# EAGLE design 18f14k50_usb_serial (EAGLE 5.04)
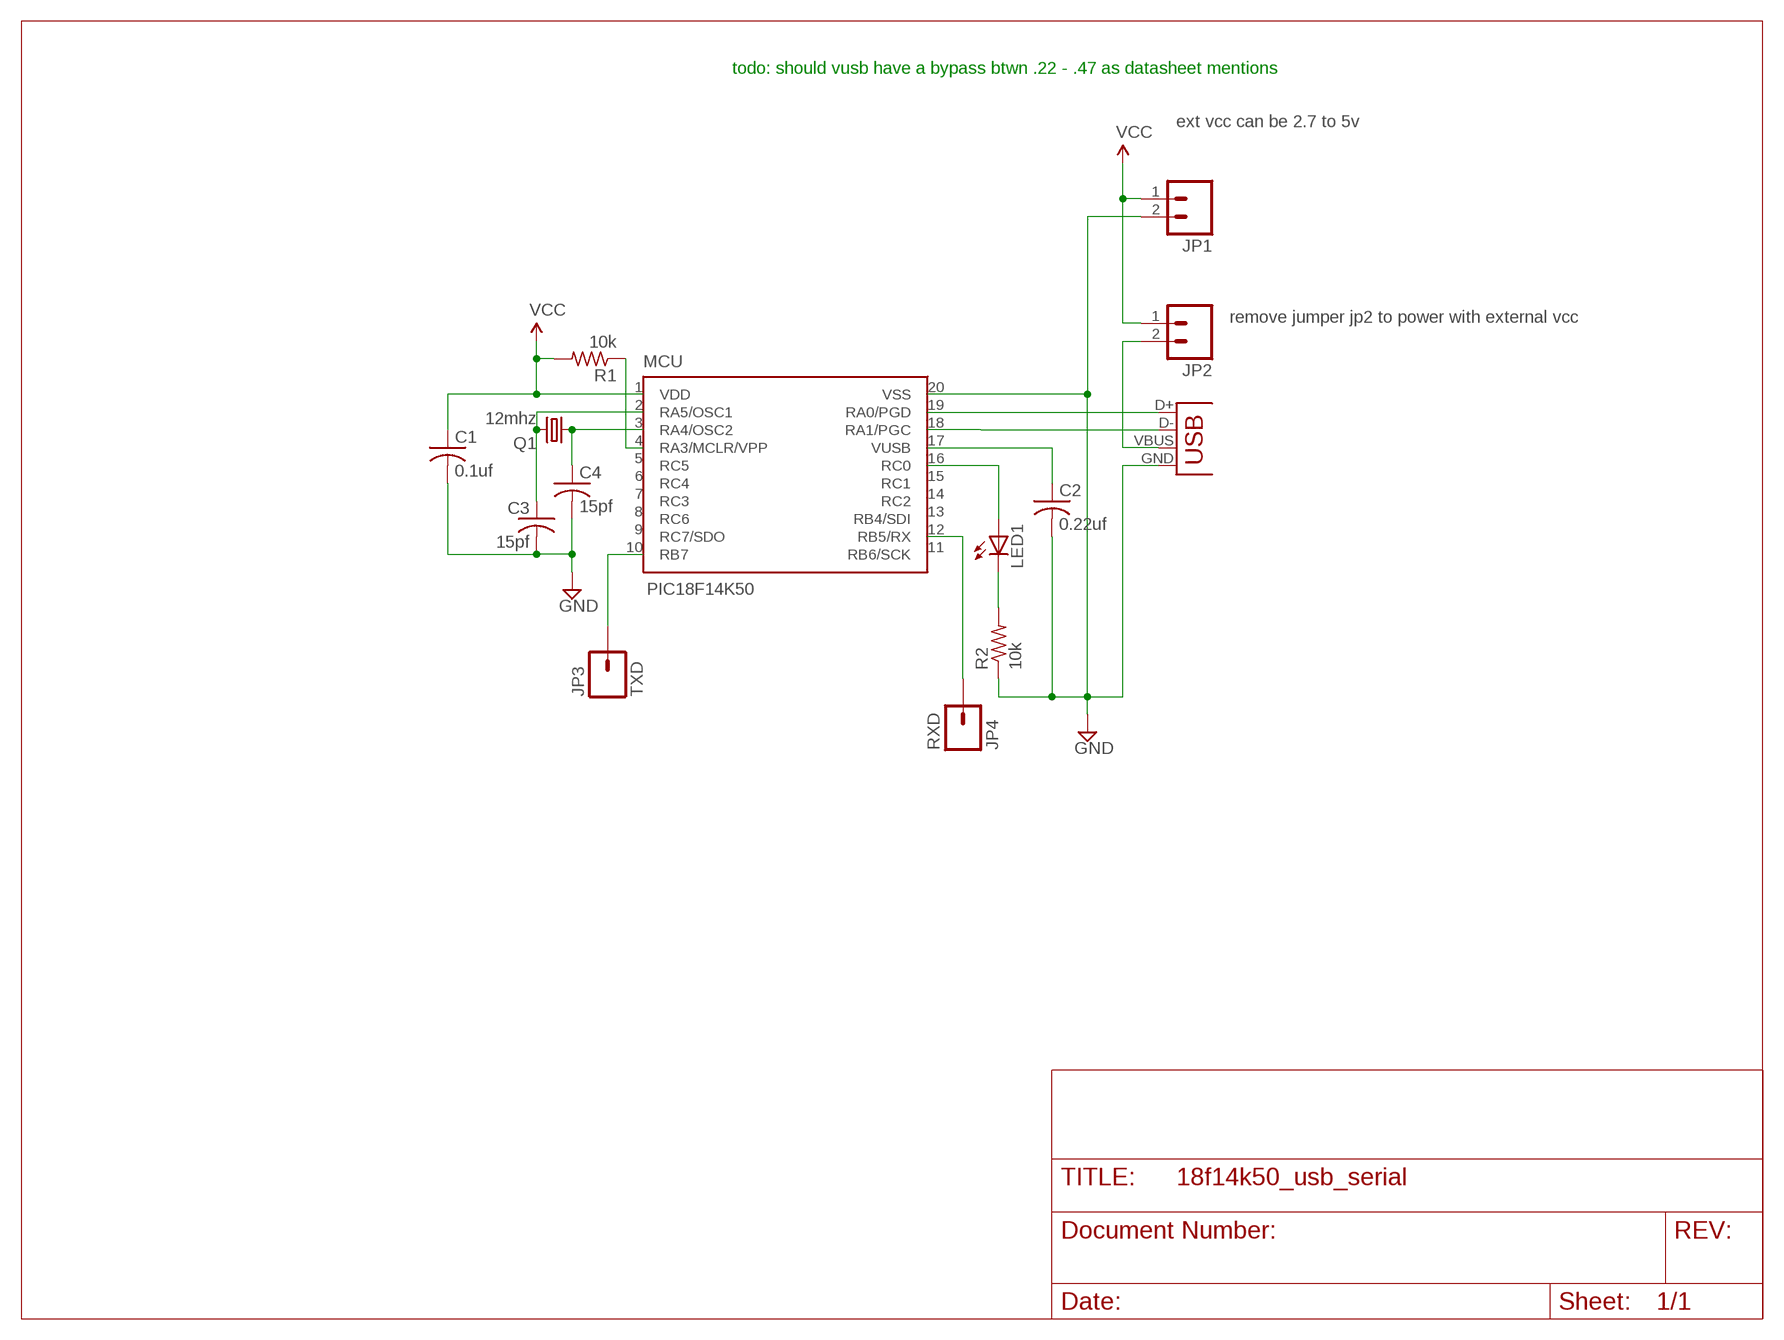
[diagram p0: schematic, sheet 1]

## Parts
C1  0.1uf  C-US025-024X044  [C025-024X044]
C2  0.22uf  C-US075-032X103  [C075-032X103]
C3  15pf  C-US025-024X044  [C025-024X044]
C4  15pf  C-US025-024X044  [C025-024X044]
JP1  M023.5MM  [SCREWTERMINAL-3.5MM-2]
JP2  M02LOCK  [1X02_LOCK]
JP3  TXD  M01PTH  [1X01]
JP4  RXD  M01PTH  [1X01]
LED1  LED5MM  [LED5MM]
MCU  PIC18F14K50  [DIL20]
Q1  12mhz  CRYSTALHC49U-V  [HC49U-V]
R1  10k  R-US_0207/12  [0207/12]
R2  10k  R-US_0207/12  [0207/12]
X1  USBSMD  [USB-MINIB]

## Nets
GND: C1.2 C2.2 C3.2 C4.2 JP1.2 MCU.20(VSS) R2.1 X1.GND
N$1: C4.1 MCU.3(RA4/OSC2) Q1.1
N$2: C3.1 MCU.2(RA5/OSC1) Q1.2
N$3: LED1.A MCU.16(RC0)
N$4: JP3.1 MCU.10(RB7)
N$5: LED1.K(C) R2.2
N$6: MCU.19(RA0/PGD) X1.D+
N$7: MCU.4(RA3/MCLR/VPP) R1.1
N$8: C2.1 MCU.17(VUSB)
N$9: MCU.18(RA1/PGC) X1.D-
N$10: JP2.2 X1.VBUS
N$11: JP4.1 MCU.12(RB5/RX)
VCC: C1.1 JP1.1 JP2.1 MCU.1(VDD) R1.2
Unconnected: MCU.5(RC5) MCU.6(RC4) MCU.7(RC3) MCU.8(RC6) MCU.9(RC7/SDO) MCU.11(RB6/SCK) MCU.13(RB4/SDI) MCU.14(RC2) MCU.15(RC1)

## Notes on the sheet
- todo: should vusb have a bypass btwn .22 - .47 as datasheet mentions
- ext vcc can be 2.7 to 5v
- remove jumper jp2 to power with external vcc

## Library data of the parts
C1-C4 = rcl:C-US: CAPACITOR, American symbol
JP1 JP2 = SparkFun:M02: Header 2
JP3 JP4 = SparkFun:M01: Header 1
LED1 = SparkFun:LED: LEDs
MCU = trl:PIC18F14K50
Q1 = crystal:CRYSTAL: CRYSTAL
R1 R2 = resistor:R-US_: RESISTOR, American symbol
X1 = SparkFun:USB: USB Connectors USB-B-PTH is fully proven SKU : PRT-00139 USB-miniB is fully proven SKU : PRT-00587 USB-A-PCB is untested. USB-A-H is throughly reviewed, but untested. Spark Fun Electronics SKU : PRT-00437 USB-B-SMT is throughly reviewed, but untested. Needs silkscreen touching up. USB-A-S has not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

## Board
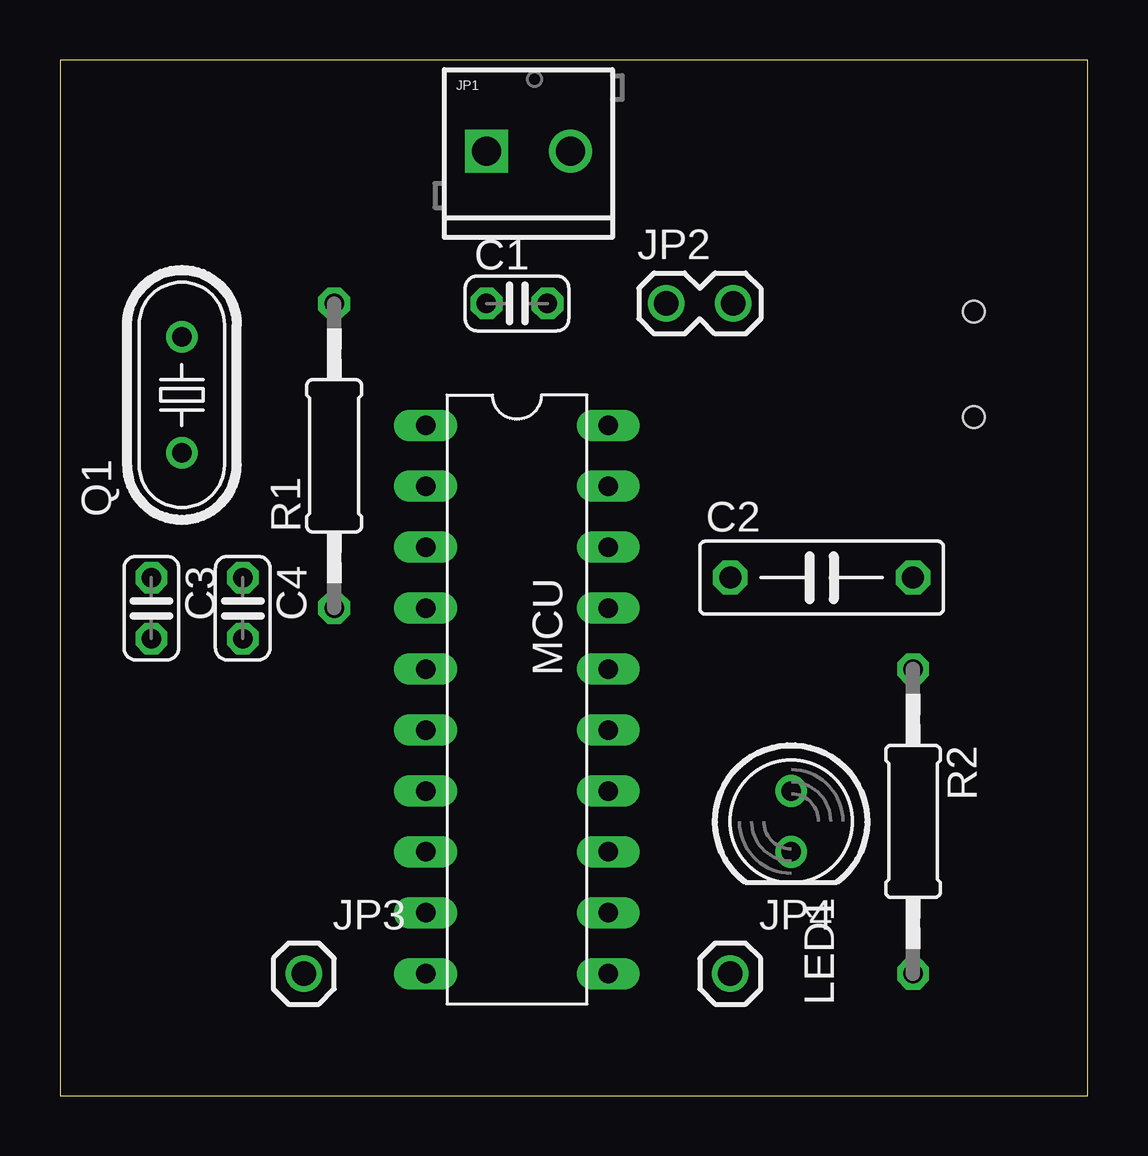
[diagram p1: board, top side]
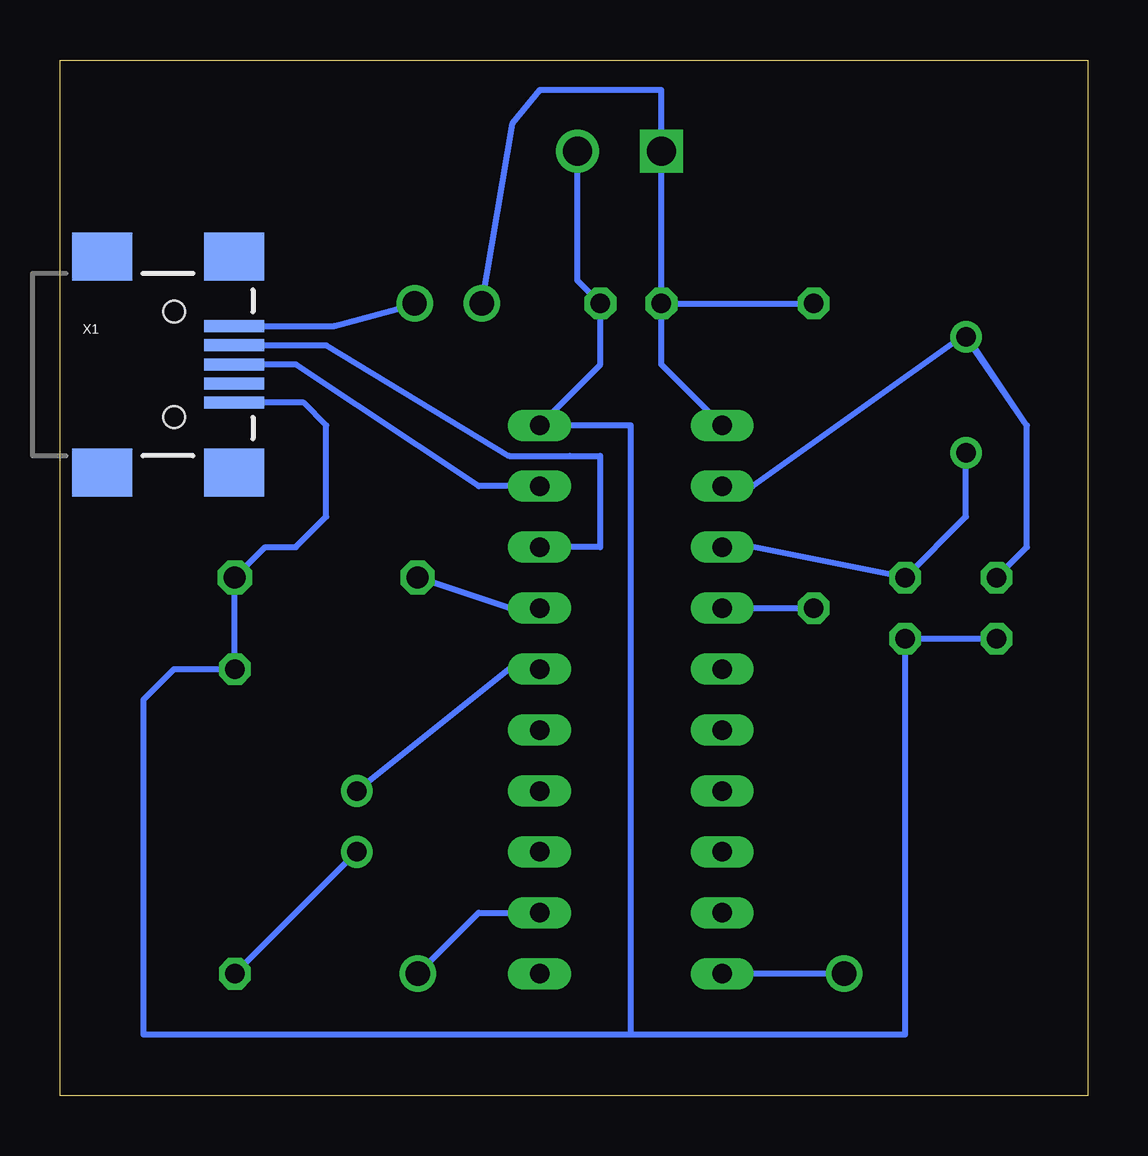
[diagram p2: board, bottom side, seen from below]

Size 42.85 x 43.17 mm. Coordinates in mm from the lower left corner, seen from the top.
Outline: 0,0 42.85,0 42.85,43.17 0,43.17 0,0
Copper layers (1*16): Top 0.035mm / dielectric 1.5mm / Bottom 0.035mm
Design rules "default": minimum track width 10mil, minimum drill 24mil, track to track 8mil, track to pad 8mil, pad to pad 8mil, via to via 8mil, smd to smd 8mil, copper to edge 40mil, drill to drill 8mil, minimum pad ring 10mil, minimum via ring 8mil, stop-mask expansion 4mil, vias tented up to drill 0mil, thermal gap 10mil

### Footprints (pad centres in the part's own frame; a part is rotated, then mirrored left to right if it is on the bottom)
C025-024X044 = drill 0.813 octagon: 1 -1.27,0; 2 1.27,0
C075-032X103 = drill 0.914 octagon: 1 -3.81,0; 2 3.81,0
SCREWTERMINAL-3.5MM-2 = drill 1.2 square: 1 0,0 | drill 1.2 round: 2 3.5,0
1X02_LOCK = drill 1.016 round: 1 -0.127,0; 2 2.667,0
1X01 = drill 1.016 round: 1 0,0
LED5MM = drill 0.813 round: A -1.27,0; K 1.27,0
DIL20 = drill 0.813 long: 1 -11.43,-3.81; 2 -8.89,-3.81; 3 -6.35,-3.81; 4 -3.81,-3.81; 5 -1.27,-3.81; 6 1.27,-3.81; 7 3.81,-3.81; 8 6.35,-3.81; 9 8.89,-3.81; 10 11.43,-3.81; 11 11.43,3.81; 12 8.89,3.81; 13 6.35,3.81; 14 3.81,3.81; 15 1.27,3.81; 16 -1.27,3.81; 17 -3.81,3.81; 18 -6.35,3.81; 19 -8.89,3.81; 20 -11.43,3.81
HC49U-V = drill 0.813 round: 1 -2.413,0; 2 2.413,0
0207/12 = drill 0.813 octagon: 1 -6.35,0; 2 6.35,0
USB-MINIB = smd 2.5 x 0.5: D+ 2.5,0; D- 2.5,0.8; GND 2.5,-1.6; ID 2.5,-0.8; VBUS 2.5,1.6 | smd 2.5 x 2: GND@1 -3,-4.5; GND@2 -3,4.5; GND@3 2.5,4.5; GND@4 2.5,-4.5 | hole 0.9: 0,2.2; 0,-2.2

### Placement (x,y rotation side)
C1  19.05,33.02 0 top
C2  31.75,21.59 0 top
C3  3.81,20.32 270 top
C4  7.62,20.32 270 top
JP1  17.78,39.37 0 top
JP2  25.4,33.02 0 top
JP3  10.16,5.08 0 top
JP4  27.94,5.08 0 top
LED1  30.48,11.43 270 top
MCU  19.05,16.51 270 top
Q1  5.08,29.21 90 top
R1  11.43,26.67 90 top
R2  35.56,11.43 270 top
X1  38.1,30.48 0 bottom

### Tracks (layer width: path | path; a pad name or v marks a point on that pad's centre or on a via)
GND
  Bottom 0.254: JP1.2 21.28,33.98 C1.2 20.32,30.48 MCU.20 19.05,27.94 19.05,15.24 19.05,2.54 | C3.2 C4.2 7.62,15.24 7.62,2.54 19.05,2.54 | X1.GND 32.69,28.88 31.75,27.94 31.75,24.13 33.02,22.86 34.29,22.86 C2.2 R2.1 38.1,17.78 39.37,16.51 39.37,2.54 19.05,2.54
N$1
  Bottom 0.254: Q1.1 5.08,24.13 C4.1 13.97,22.86 MCU.3
N$2
  Bottom 0.254: C3.1 2.54,22.86 2.54,27.94 | 2.54,27.94 Q1.2 2.54,27.94 | 2.54,27.94 5.08,31.75 13.97,25.4 MCU.2
N$3
  Bottom 0.254: LED1.A 24.13,17.78 MCU.16
N$4
  Bottom 0.254: JP3.1 MCU.10
N$5
  Bottom 0.254: R2.2 LED1.K
N$6
  Bottom 0.254: X1.D+ 33.02,30.48 25.4,25.4 24.13,25.4 MCU.19
N$7
  Bottom 0.254: MCU.4 R1.1
N$8
  Bottom 0.254: C2.1 24.13,20.32 MCU.17
N$9
  Bottom 0.254: MCU.18 20.32,22.86 20.32,26.67 21.59,26.67 24.13,26.67 31.75,31.28 X1.D-
N$10
  Bottom 0.254: X1.VBUS 31.42,32.08 27.94,33.02 JP2.2
N$11
  Bottom 0.254: JP4.1 25.4,7.62 MCU.12
VCC
  Bottom 0.254: C1.1 R1.2 | C1.1 17.78,30.48 MCU.1 | C1.1 JP1.1 17.78,41.91 22.86,41.91 24,40.51 JP2.1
